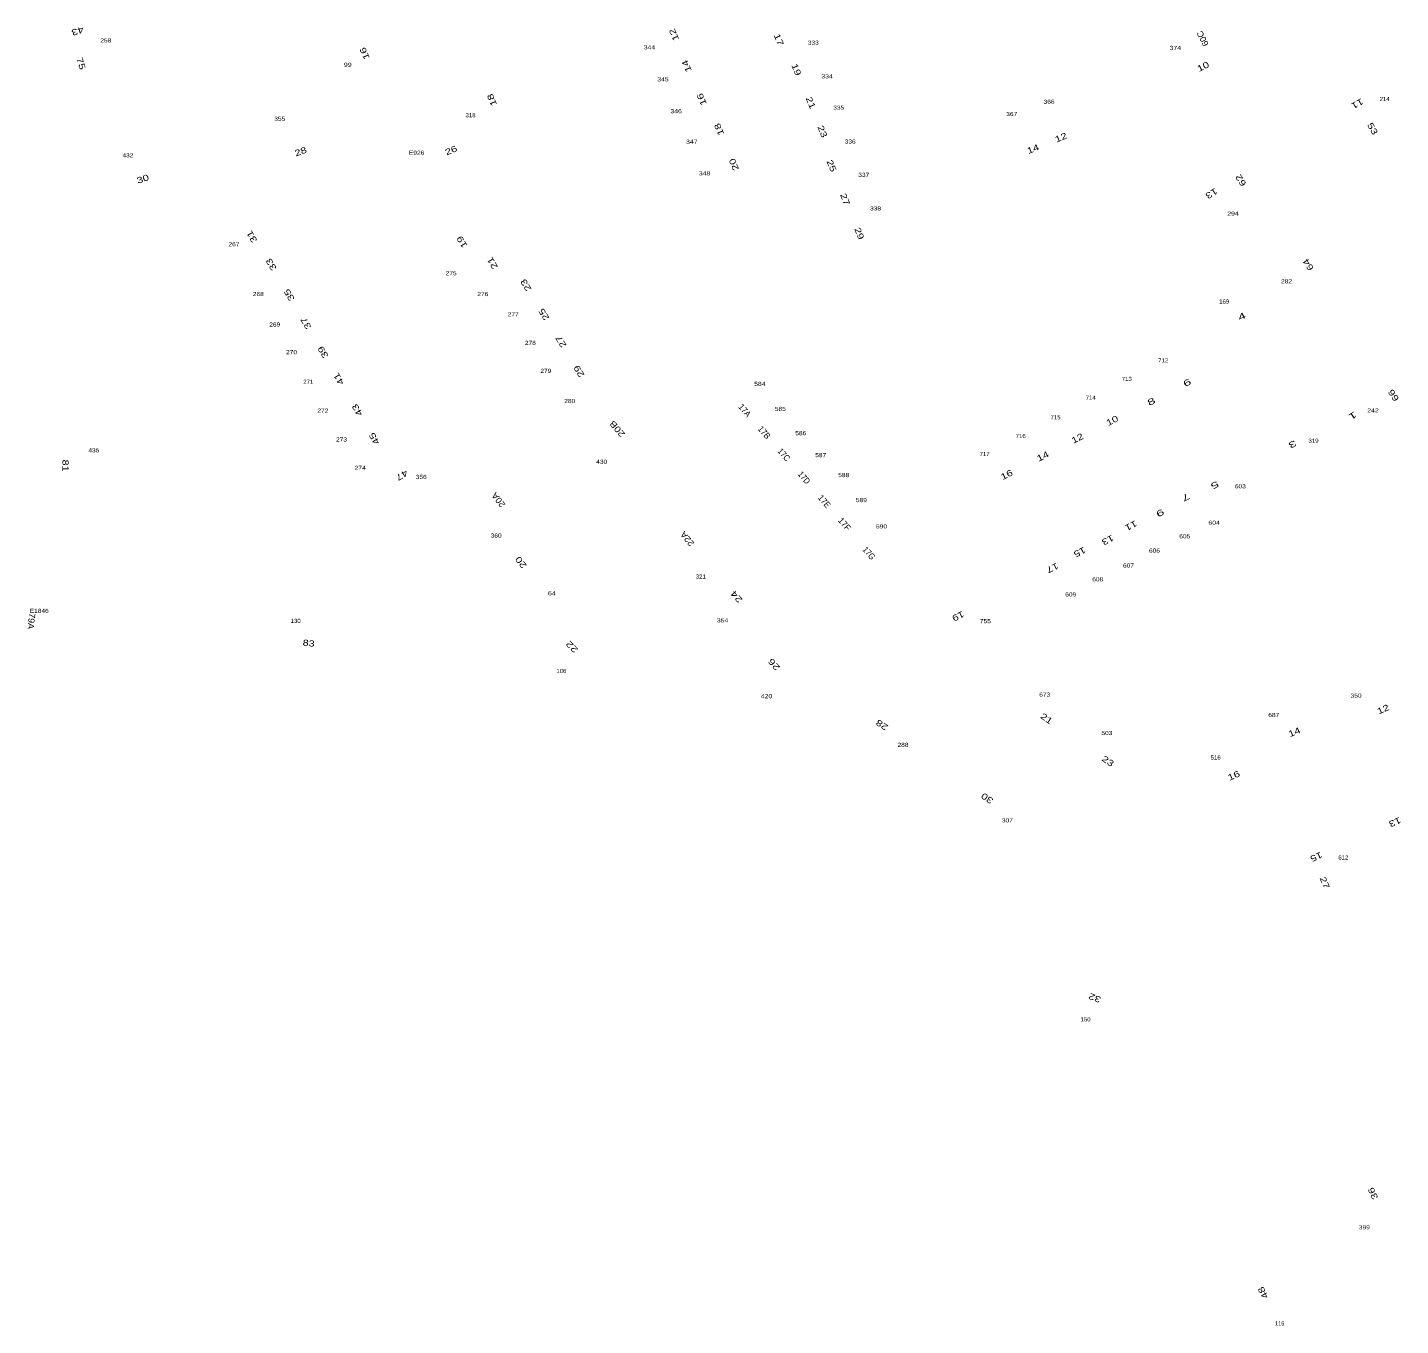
# Model space of a CAD drawing. Extents: x -828673 to -815583, y -1077737 to -1063807.
# Drawn here: x -821192.6 to -820857.9, y -1073903 to -1073586.6 of the extents above; entities that cross this region are included whole.
import ezdxf
from ezdxf.enums import TextEntityAlignment as Align

# ---------------------------------------------------------------- set-up
doc = ezdxf.new("R2010")
doc.units = 0
doc.header["$LTSCALE"] = 0.4
doc.layers.add('1', color=7, linetype='Continuous')
doc.layers.add('2', color=7, linetype='Continuous')

msp = doc.modelspace()

# ---------------------------------------------------------------- texts
at = {"layer": '1'}
for s, width, p in [('258', 1.2, (-821173.489, -1073590.263)), ('344', 1.25, (-821040.99, -1073591.942)), ('333', 1.2, (-821001.057, -1073590.805)), ('374', 1.25, (-820912.808, -1073592.095)), ('99', 1.3, (-821114.525, -1073596.208)), ('345', 1.25, (-821037.683, -1073599.747)), ('334', 1.25, (-820997.699, -1073599.023)), ('335', 1.2, (-820994.857, -1073606.66)), ('214', 1.1, (-820861.797, -1073604.541)), ('355', 1.2, (-821131.094, -1073609.364)), ('318', 1.1, (-821084.601, -1073608.492)), ('346', 1.25, (-821034.484, -1073607.522)), ('347', 1.25, (-821030.661, -1073614.965)), ('336', 1.2, (-820992.071, -1073614.914)), ('432', 1.2, (-821168.119, -1073618.284)), ('E926', 1.2, (-821097.75, -1073617.65)), ('348', 1.25, (-821027.562, -1073622.667)), ('337', 1.2, (-820988.765, -1073623.029)), ('338', 1.2, (-820985.88, -1073631.217)), ('294', 1.25, (-820898.757, -1073632.482)), ('267', 1.2, (-821142.26, -1073639.946)), ('275', 1.2, (-821089.322, -1073647.018)), ('282', 1.2, (-820885.712, -1073648.982)), ('268', 1.2, (-821136.327, -1073652.091)), ('276', 1.2, (-821081.601, -1073652.092)), ('169', 1.1, (-820900.911, -1073653.908)), ('269', 1.2, (-821132.315, -1073659.513)), ('277', 1.2, (-821074.183, -1073657.015)), ('270', 1.2, (-821128.228, -1073666.254)), ('278', 1.2, (-821070.02, -1073663.982)), ('712', 1.1, (-820915.784, -1073668.268)), ('271', 1.1, (-821124.141, -1073673.449)), ('279', 1.2, (-821066.235, -1073670.798)), ('713', 1.1, (-820924.645, -1073672.762)), ('584', 1.25, (-821014.078, -1073673.98)), ('280', 1.2, (-821060.407, -1073678.145)), ('585', 1.2, (-821009.093, -1073680.075)), ('714', 1.1, (-820933.445, -1073677.318)), ('272', 1.2, (-821120.583, -1073680.492)), ('715', 1.1, (-820941.999, -1073682.121)), ('242', 1.25, (-820864.635, -1073680.447)), ('586', 1.2, (-821004.109, -1073685.986)), ('716', 1.1, (-820950.491, -1073686.677)), ('435', 1.2, (-821176.414, -1073690.169)), ('273', 1.2, (-821116.041, -1073687.535)), ('319', 1.1, (-820879.135, -1073687.826)), ('430', 1.2, (-821052.63, -1073692.961)), ('587', 1.2, (-820999.247, -1073691.343)), ('717', 1.1, (-820959.29, -1073691.049)), ('274', 1.25, (-821111.5, -1073694.427)), ('356', 1.2, (-821096.611, -1073696.646)), ('588', 1.2, (-820993.647, -1073696.207)), ('603', 1.2, (-820896.97, -1073698.929)), ('589', 1.2, (-820989.34, -1073702.302)), ('590', 1.2, (-820984.417, -1073708.706)), ('604', 1.25, (-820903.35, -1073707.8)), ('360', 1.2, (-821078.349, -1073710.937)), ('605', 1.2, (-820910.517, -1073711.116)), ('606', 1.2, (-820917.891, -1073714.598)), ('607', 1.2, (-820924.23, -1073718.246)), ('321', 1.1, (-821028.468, -1073720.933)), ('608', 1.2, (-820931.729, -1073721.603)), ('64', 1.3, (-821064.772, -1073725.023)), ('609', 1.2, (-820938.316, -1073725.293)), ('E1846', 1.2, (-821189.716, -1073729.297)), ('130', 1.1, (-821127.223, -1073731.73)), ('354', 1.25, (-821023.169, -1073731.612)), ('755', 1.2, (-820959.115, -1073731.8)), ('106', 1.1, (-821062.453, -1073743.957)), ('420', 1.25, (-821012.447, -1073750.085)), ('673', 1.2, (-820944.659, -1073749.703)), ('350', 1.2, (-820868.76, -1073749.951)), ('687', 1.2, (-820888.812, -1073754.677)), ('503', 1.2, (-820929.495, -1073759.071)), ('288', 1.2, (-820979.191, -1073761.951)), ('516', 1.1, (-820902.981, -1073765.04)), ('307', 1.2, (-820953.753, -1073780.356)), ('612', 1.1, (-820871.862, -1073789.404)), ('150', 1.1, (-820934.696, -1073828.856)), ('399', 1.2, (-820866.749, -1073879.533))]:
    msp.add_text(s, height=1, dxfattribs=dict(at, width=width)).set_placement(p, align=Align.CENTER)
at = {"layer": '1', "width": 1.2}
for s, rotation, p in [('366', 0.641, (-820943.5951, -1073605.2231)), ('367', 359.708, (-820952.687, -1073608.2208))]:
    msp.add_text(s, height=1, rotation=rotation, dxfattribs=at).set_placement(p, align=Align.CENTER)
at = {"layer": '1'}
msp.add_text('116', height=1, dxfattribs=at).set_placement((-820887.374, -1073902.962), align=Align.CENTER)
at = {"layer": '2'}
for s, rotation, width, p in [('43', 197.611, 1.35, (-821180.5796, -1073586.7861)), ('12', 112.749, 1.35, (-821034.3245, -1073588.108)), ('17', 292.898, 1.35, (-821010.1528, -1073589.8707)), ('60C', 116.473, 1.05, (-820905.4723, -1073588.9933)), ('16', 112.966, 1.35, (-821109.7291, -1073592.6596)), ('75', 287.106, 1.35, (-821180.2359, -1073595.6144)), ('14', 112.759, 1.35, (-821031.2297, -1073595.7391)), ('19', 292.652, 1.35, (-821005.8678, -1073597.1602)), ('10', 26.414, 1.35, (-820905.7091, -1073596.816)), ('18', 112.15, 1.35, (-821078.7016, -1073603.9968)), ('16', 112.745, 1.35, (-821027.5624, -1073603.855)), ('21', 292.679, 1.35, (-821002.3544, -1073605.2233)), ('11', 209.401, 1.35, (-820868.8018, -1073604.5457)), ('18', 112.62, 1.35, (-821023.3333, -1073611.168)), ('23', 292.716, 1.35, (-820999.5133, -1073612.2354)), ('12', 22.297, 1.35, (-820940.4131, -1073614.1167)), ('53', 299.494, 1.35, (-820865.3881, -1073611.6528)), ('26', 22.43, 1.35, (-821089.0612, -1073617.2514)), ('14', 22.263, 1.35, (-820947.2326, -1073616.9085)), ('28', 20.355, 1.35, (-821125.7474, -1073617.5525)), ('20', 112.892, 1.35, (-821019.7241, -1073619.7252)), ('25', 292.679, 1.35, (-820997.2934, -1073620.6073)), ('62', 122.796, 1.35, (-820896.2232, -1073623.4707)), ('30', 19.067, 1.35, (-821164.2215, -1073624.235)), ('13', 212.937, 1.35, (-820904.3917, -1073626.4426)), ('27', 292.716, 1.35, (-820993.9853, -1073628.7754)), ('29', 292.519, 1.35, (-820990.5263, -1073637.0958)), ('31', 120, 1.35, (-821137.2661, -1073637.238)), ('19', 120.601, 1.35, (-821086.0444, -1073638.5163)), ('21', 120.856, 1.35, (-821078.6296, -1073643.6662)), ('33', 120.55, 1.35, (-821132.5541, -1073644.0147)), ('64', 123.034, 1.35, (-820879.793, -1073644.0354)), ('23', 121.585, 1.35, (-821070.4797, -1073649.0353)), ('35', 120.615, 1.35, (-821128.1647, -1073651.4364)), ('25', 121.645, 1.35, (-821066.0892, -1073656.155)), ('37', 120.565, 1.35, (-821124.0775, -1073658.3279)), ('4', 27.325, 1.7, (-820896.2603, -1073657.7006)), ('27', 121.547, 1.35, (-821061.9248, -1073662.8179)), ('39', 120.505, 1.35, (-821119.913, -1073665.3722)), ('29', 121.617, 1.35, (-821057.5355, -1073670.0127)), ('41', 120.541, 1.35, (-821116.0939, -1073671.9136)), ('6', 27.035, 1.7, (-820909.5944, -1073673.847)), ('66', 123.248, 1.35, (-820859.009, -1073675.8682)), ('43', 120.576, 1.35, (-821111.5758, -1073679.479)), ('17A', 310.854, 0.95, (-821018.3241, -1073680.4439)), ('8', 26.963, 1.7, (-820918.3306, -1073678.4659)), ('20B', 130.281, 1.25, (-821048.2779, -1073683.9654)), ('10', 27.016, 1.35, (-820927.8512, -1073683.1052)), ('1', 213.237, 1.7, (-820869.9599, -1073680.5938)), ('45', 120.585, 1.35, (-821107.412, -1073686.4461)), ('17B', 310.823, 0.95, (-821013.5847, -1073685.8017)), ('12', 26.99, 1.35, (-820936.3439, -1073687.4149)), ('17C', 310.876, 0.9, (-821008.7855, -1073691.2187)), ('3', 207.332, 1.7, (-820884.5936, -1073687.5375)), ('81', 270, 1.3, (-821184.051, -1073693.383)), ('14', 26.99, 1.35, (-820944.7749, -1073691.7869)), ('47', 210.8, 1.35, (-821101.688, -1073695.1089)), ('17D', 310.833, 0.9, (-821003.8623, -1073696.8216)), ('16', 26.998, 1.35, (-820953.5745, -1073696.2804)), ('5', 207.617, 1.7, (-820903.5483, -1073697.4831)), ('20A', 127.82, 1.1, (-821077.2136, -1073701.3179)), ('17E', 310.802, 0.95, (-820998.9383, -1073702.6099)), ('7', 207.577, 1.7, (-820910.5903, -1073700.4663)), ('9', 207.509, 1.7, (-820916.8471, -1073704.2795)), ('22A', 128.759, 1.1, (-821031.1927, -1073710.785)), ('11', 207.73, 1.35, (-820923.9435, -1073707.3843)), ('13', 207.266, 1.35, (-820929.6034, -1073710.868)), ('20', 128.032, 1.35, (-821071.7287, -1073716.5231)), ('17G', 310.805, 0.9, (-820988.0472, -1073715.2319)), ('15', 206.743, 1.35, (-820936.441, -1073713.8053)), ('17', 206.675, 1.35, (-820943.0683, -1073717.6604)), ('24', 131.481, 1.4, (-821019.2173, -1073724.8593)), ('79A', 263.526, 1.1, (-821192.3697, -1073731.2154)), ('19', 206.687, 1.35, (-820966.0712, -1073729.4367)), ('83', 353.898, 1.3, (-821124.1282, -1073737.4071)), ('22', 134.58, 1.4, (-821059.3529, -1073737.0579)), ('26', 131.791, 1.4, (-821010.0881, -1073741.3653)), ('12', 23.587, 1.35, (-820861.8856, -1073753.4657)), ('28', 146.511, 1.35, (-820983.9172, -1073755.9807)), ('21', 325.147, 1.35, (-820944.6146, -1073755.6603)), ('14', 23.016, 1.35, (-820883.5112, -1073759.0268)), ('23', 326.136, 1.35, (-820929.6574, -1073766.0373)), ('16', 23.433, 1.35, (-820898.2598, -1073769.6343)), ('30', 145.501, 1.35, (-820958.2502, -1073773.8689)), ('13', 203.31, 1.35, (-820859.5622, -1073779.6016)), ('15', 204.073, 1.35, (-820878.7561, -1073788.0625)), ('27', 292.908, 1.35, (-820877.0865, -1073795.3256)), ('32', 158.441, 1.35, (-820932.1639, -1073822.4423)), ('36', 115.418, 1.35, (-820863.9689, -1073870.4734)), ('48', 118.504, 1.35, (-820890.7581, -1073894.6319))]:
    msp.add_text(s, height=1.5, rotation=rotation, dxfattribs=dict(at, width=width)).set_placement(p, align=Align.CENTER)
msp.add_text('17F', height=1.5, rotation=310.918, dxfattribs=at).set_placement((-820994.018, -1073708.1513), align=Align.CENTER)

doc.saveas('drawing.dxf')
